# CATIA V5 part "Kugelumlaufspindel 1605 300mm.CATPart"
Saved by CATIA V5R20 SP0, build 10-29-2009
Part number: Kugelumlaufspindel 1605 350mm
Bounding box of the stored display mesh (mm): x -8 to 8, y 0 to 350, z -8 to 8
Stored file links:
  C:\Users\Andi\Desktop\Offene Projekte\Plasmacutter\Z-Achse\Kugelumlaufspindel 1605 300mm.CATPart
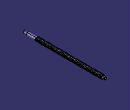
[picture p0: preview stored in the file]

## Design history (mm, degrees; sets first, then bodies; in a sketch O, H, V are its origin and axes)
AxisSystem1: origin (0, 0, 0), X (1, 0, 0), Y (0, 1, 0), Z (0, 0, 1)
AxisSystem2: origin (0, 0, 0), X (1, 0, 0), Y (0, 1, 0), Z (0, 0, 1)
Body1 (main body)
  Sketch1 on YZ plane of AxisSystem1, origin (0, 0, 0), H (0, 1, 0), V (0, 0, 1)
    line L1 (0, 0) -> (0, 5)
    point P1 (0, 5)
    line L2 (0, 5) -> (15, 5)
    line L3 (15, 5) -> (15, 6)
    point P3 (15, 6)
    line L4 (15, 6) -> (54, 6)
    line L5 (54, 6) -> (54, 8)
    point P5 (54, 8)
    line L6 (54, 8) -> (339, 8)
    line L7 (339, 8) -> (339, 5)
    point P7 (339, 5)
    line L8 (339, 5) -> (347, 5)
    line L9 (347, 5) -> (347, 4.8)
    line L10 (347, 4.8) -> (348.15, 4.8)
    line L11 (348.15, 4.8) -> (348.15, 5)
    point P11 (348.15, 5)
    line L12 (348.15, 5) -> (350, 5)
    line L13 (350, 5) -> (350, 0)
    point P13 (350, 0)
    line L14 (350, 0) -> (0, 0)
    distance P1 H = 5
    length L2 = 15
    distance P3 H = 6
    length L4 = 39
    distance P5 H = 8
    distance P7 H = 5
    length L8 = 8
    length L10 = 1.15
    distance L10 L14 = 4.8
    distance L13 L7 = 11
    distance L13 V = 350
    vertical: L1 V, L3 V, L5 V, L7 V, L9 V, L11 V, L13 V
    horizontal: L2 H, L4 H, L6 H, L8 H, L10 H, L12 H, L14 H
    coincidence: P11 L8, P13 H
  Shaft1: profile Sketch1, axis edge [YZ plane of AxisSystem1 | XY plane of AxisSystem1], angle 360
  Sketch2 on xy-plane, origin (0, 0, 0), H (1, 0, 0), V (0, 1, 0)
    arc A1 centre (8.5, 341) radius 2 from (8.5, 343) to (8.5, 339) ccw
    point P1 (8.5, 341)
    line L1 (8.5, 339) -> (8.5, 343)
    reference intersected line E1 through (0, 0) direction (0, 1) from yz-plane
    reference projected line E2 (-8, 339) -> (8, 339) from edge [face of Shaft1 from Sketch1.L6 | face of Shaft1 from Sketch1.L7]
    distance E1 L1 = 8.5
    radius A1 = 2
    distance P1 E2 = 2
    vertical: L1 V
    coincidence: P1 L1
  Helix1: Direction edge [YZ plane of AxisSystem2 | XY plane of AxisSystem2], RefPoint vertex [element of Sketch2 | element of Sketch2], Pitch 5, Height 415, TaperAngle 0
  Slot1: profile Sketch2, centre curve Helix1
